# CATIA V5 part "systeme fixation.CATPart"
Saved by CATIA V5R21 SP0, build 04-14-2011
Part number: FixationJustine
Bounding box of the stored display mesh (mm): x -25 to 25, y 0 to 68.95, z 0 to 3
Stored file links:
  C:\Users\2027.DESARCY-LEMIE30\Desktop\V15(20.03.2023)\systeme fixation.CATPart
  C:\Program Files\Dassault Systemes\B21\win_b64\reffiles\standard\MetricThickPitch.txt
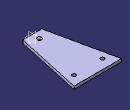
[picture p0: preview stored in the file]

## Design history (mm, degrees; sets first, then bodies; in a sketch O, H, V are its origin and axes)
Body1 (main body)
  Sketch1 on xy-plane, origin (0, 0, 0), H (1, 0, 0), V (0, 1, 0)
    construction line L1 (0, 81.499) -> (0, -38.501)
    point P1 (0, 81.499)
    line L2 (-25, 68.95) -> (25, 68.95)
    point P4 (25, 68.95)
    line L3 (25, 68.95) -> (10, 0)
    point P5 (10, 0)
    line L4 (10, 0) -> (-10, 0)
    point P6 (-10, 0)
    line L5 (-10, 0) -> (-25, 68.95)
    axis line L6 (-40, 58.95) -> (40, 58.95)
    length L2 = 50
    distance L1 P4 = 25
    length L4 = 20
    distance L1 P6 = 10
    distance L4 L2 = 68.95
    distance L6 L2 = 10
    coincidence: P1 V, P5 H
    vertical: L1 V
    horizontal: L2 H, L4 H, L6 H
  Pad1: profile Sketch1, direction (0, 0, 1), length 3
  Sketch2 on end face of Pad1, origin (-0.4128, 9.8194, 3), H (1, 0, 0), V (0, 1, 0)
    point P1 (0.4128, -2.3194)
    reference projected line E1 (-9.5872, -9.8194) -> (10.4128, -9.8194) from edge [face of Pad1 from Sketch1.L4 | end face of Pad1]
    reference projected point E2 (-9.5872, -9.8194) from vertex [face of Pad1 from Sketch1.L4 | end face of Pad1 | face of Pad1 from Sketch1.L5]
    distance P1 E1 = 7.5
    distance E2 P1 H = 10
  Hole1: placed by Sketch2, at (0, 7.5, 3) direction (0, 0, -1), diameter 4.917, through (limit type 6), threaded "M6", thread diameter 6, thread depth 3, pitch 1
  Sketch3 on end face of Pad1, origin (0, 0, 3), H (1, 0, 0), V (0, 1, 0)
    circle A1 centre (-15, 58.95) radius 2
    point P1 (-15, 58.95)
    reference projected line E1 (25, 68.95) -> (-25, 68.95) from edge [face of Pad1 from Sketch1.L2 | end face of Pad1]
    reference projected point E2 (-25, 68.95) from vertex [face of Pad1 from Sketch1.L2 | end face of Pad1 | face of Pad1 from Sketch1.L5]
    circle A2 centre (15, 58.95) radius 2
    point P2 (15, 58.95)
    reference projected line E3 (25, 68.95) -> (-25, 68.95) from edge [face of Pad1 from Sketch1.L2 | end face of Pad1]
    radius A1 = 2
    distance P1 E1 = 10
    distance P1 E2 H = 10
    radius A2 = 2
    distance P2 E3 = 10
    distance P1 P2 = 30
  Pocket1: profile Sketch3, direction (0, 0, -1), length 3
